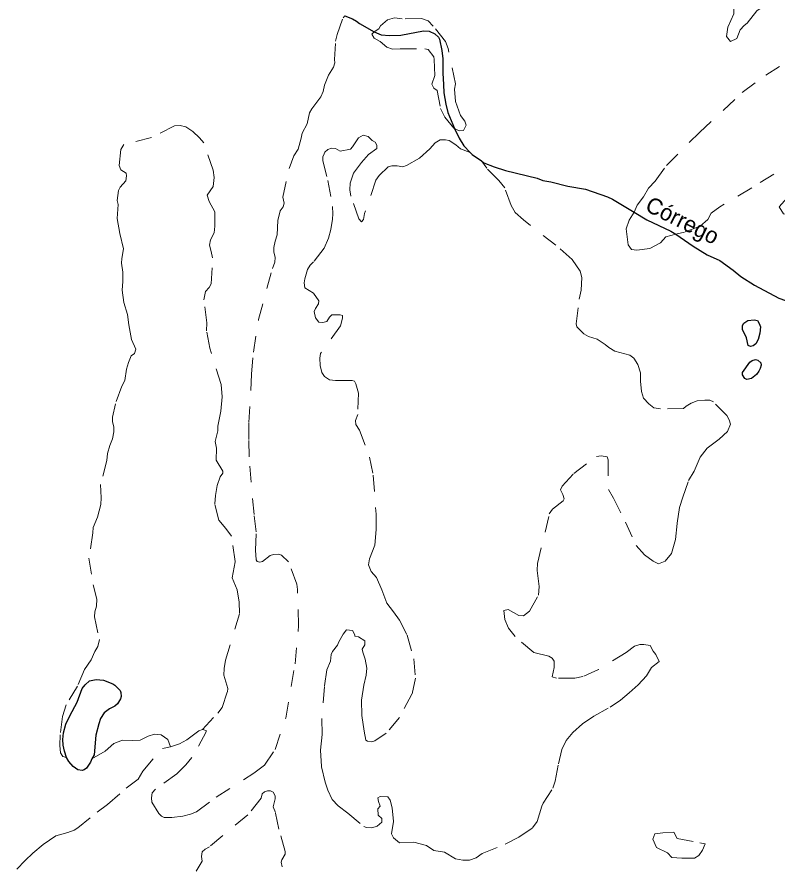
# Model space of a CAD drawing. Extents: x 344.9 to 371, y 7566.4 to 7594.3.
# Drawn here: x 357.38 to 362.09, y 7580.3 to 7585.54 of the extents above; entities that cross this region are included whole.
import ezdxf
from ezdxf.enums import TextEntityAlignment as Align

# ---------------------------------------------------------------- set-up
doc = ezdxf.new("R2010")
doc.units = 0
doc.header["$LTSCALE"] = 0.04
doc.linetypes.add('LONG_DASHED', pattern=[7.5, 6, -1.5])
doc.linetypes.add('SHORT_DASHED', pattern=[2.7, 1.5, -1.2])
for name, color, linetype, lineweight in [('17', 7, 'SHORT_DASHED', 13), ('2', 7, 'Continuous', 25), ('21', 7, 'SHORT_DASHED', 13), ('3', 7, 'LONG_DASHED', 25), ('7', 7, 'Continuous', 25)]:
    doc.layers.add(name, color=color, linetype=linetype, lineweight=lineweight)
doc.layers.add('61', color=7, linetype='Continuous')

msp = doc.modelspace()

# ---------------------------------------------------------------- linework, layer by layer
at = {"layer": '17'}
for points in [[(358.5305, 7581.1294), (358.624, 7581.2313), (358.6522, 7581.266), (358.684, 7581.3637), (358.6877, 7581.384), (358.6618, 7581.4653), (358.6636, 7581.507), (358.6729, 7581.5587), (358.7596, 7581.8497), (358.7577, 7581.9172), (358.7448, 7581.9948), (358.7134, 7582.0687), (358.7319, 7582.1694), (358.7097, 7582.3256), (358.6747, 7582.3736), (358.6304, 7582.4254), (358.6064, 7582.5261), (358.6101, 7582.5779), (358.6202, 7582.6401), (358.6396, 7582.6933), (358.6562, 7582.7154), (358.6562, 7582.7293), (358.6147, 7582.7954), (358.6165, 7582.8716), (358.6082, 7582.9122), (358.6239, 7582.9783), (358.6248, 7583.0078), (358.6433, 7583.0997), (358.6507, 7583.1889), (358.6445, 7583.2656), (358.5749, 7583.4905), (358.5548, 7583.5963), (358.5557, 7583.6469), (358.5391, 7583.7889), (358.5487, 7583.8395), (358.5714, 7583.8643), (358.5836, 7583.887), (358.5923, 7584.0482), (358.5845, 7584.0879), (358.5723, 7584.1262), (358.5793, 7584.1593), (358.6011, 7584.2029), (358.6054, 7584.2443), (358.6063, 7584.3341), (358.5706, 7584.3968), (358.5593, 7584.4369), (358.5959, 7584.4901), (358.6012, 7584.5454), (358.5951, 7584.5908), (358.5376, 7584.7603), (358.5123, 7584.7908), (358.4696, 7584.83), (358.4261, 7584.8597), (358.3921, 7584.8684), (358.3572, 7584.8649), (358.2152, 7584.793), (358.0427, 7584.7507), (358.0244, 7584.7185), (358.0148, 7584.6209), (358.0235, 7584.5921), (358.0566, 7584.5729), (358.0601, 7584.5568), (358.0558, 7584.5254), (358.02, 7584.4853), (358.0096, 7584.4653), (358.0026, 7584.4025), (358.0087, 7584.3781), (358.0018, 7584.2923), (358.0184, 7584.199), (358.0402, 7584.1036), (358.0297, 7584.0453), (358.0288, 7584.0156), (358.0376, 7583.959), (358.0376, 7583.9015), (358.0333, 7583.8488), (358.0429, 7583.773), (358.0656, 7583.6976), (358.0735, 7583.6348), (358.09, 7583.5433), (358.117, 7583.4823), (358.1092, 7583.4566), (358.0883, 7583.4426), (358.0717, 7583.4008)], [(358.0717, 7583.4008), (358.0595, 7583.359), (358.0482, 7583.2884), (358.0316, 7583.2535), (357.9907, 7583.145), (357.9724, 7583.0631), (357.9733, 7583.0339), (357.9812, 7583.0034), (357.9803, 7582.9711), (357.9733, 7582.9284), (357.9567, 7582.8875), (357.9419, 7582.8369), (357.9384, 7582.7933), (357.8992, 7582.6465), (357.9037, 7582.5632), (357.901, 7582.5214), (357.8801, 7582.4438), (357.8531, 7582.3802), (357.8522, 7582.3471), (357.8272, 7582.1903), (357.8532, 7582.0255), (357.875, 7581.9366), (357.8733, 7581.8926), (357.8628, 7581.8586), (357.862, 7581.8264), (357.8916, 7581.6873), (357.8829, 7581.6437), (357.8637, 7581.6115), (357.8402, 7581.5601), (357.7993, 7581.4999), (357.7566, 7581.3984), (357.6852, 7581.2825), (357.6635, 7581.2106), (357.6496, 7581.0968), (357.6461, 7581.0315), (357.6505, 7580.9844), (357.6653, 7580.9635), (357.6886, 7580.9566)], [(357.846, 7580.9479), (357.9268, 7580.9965), (357.9811, 7581.0433), (358.034, 7581.0644), (358.0989, 7581.0614), (358.1442, 7581.0644), (358.194, 7581.0886), (358.2333, 7581.1006), (358.2741, 7581.0976), (358.3163, 7581.0674), (358.3319, 7581.0215)]]:
    msp.add_lwpolyline(points, dxfattribs=at)
at = {"layer": '2'}
for points in [[(361.9681, 7583.544), (361.955, 7583.5169), (361.9384, 7583.5042), (361.9209, 7583.5002), (361.9066, 7583.5066), (361.8971, 7583.5542), (361.8724, 7583.605), (361.8716, 7583.6289), (361.8804, 7583.6432), (361.9042, 7583.6598), (361.9447, 7583.6646), (361.9645, 7583.6598), (361.9749, 7583.6424), (361.9823, 7583.6208), (361.9788, 7583.582)], [(361.9269, 7583.3017), (361.8996, 7583.2962), (361.8867, 7583.3008), (361.8713, 7583.3241), (361.8727, 7583.3389), (361.9167, 7583.4028), (361.9319, 7583.4139), (361.9518, 7583.419), (361.9662, 7583.4153), (361.9856, 7583.3981), (361.987, 7583.3842), (361.9809, 7583.3629), (361.9735, 7583.3467), (361.9587, 7583.3272)]]:
    msp.add_lwpolyline(points, close=True, dxfattribs=at)
at = {"layer": '21'}
for points in [[(362.1042, 7585.6456), (362.0474, 7585.6125), (361.9883, 7585.5959), (361.9599, 7585.577), (361.9008, 7585.5013), (361.8818, 7585.4871), (361.8582, 7585.4587), (361.8369, 7585.4067), (361.7967, 7585.3878), (361.773, 7585.4185), (361.7801, 7585.4753), (361.818, 7585.5581), (361.818, 7585.5912), (361.8132, 7585.6267), (361.7896, 7585.6952)], [(359.0196, 7582.2093), (358.9991, 7582.2152), (358.9694, 7582.2133), (358.949, 7582.2067), (358.9002, 7582.1691), (358.8843, 7582.1644), (358.8685, 7582.1697), (358.8626, 7582.179), (358.8586, 7582.2397), (358.8626, 7582.3528), (358.8488, 7582.4603), (358.8184, 7582.8171), (358.8164, 7582.9247), (358.817, 7583.0285), (358.8341, 7583.3295), (358.8453, 7583.4641), (358.8769, 7583.6663), (358.9621, 7583.9825), (358.9779, 7584.0221), (358.9792, 7584.0512), (358.9724, 7584.0863), (358.9724, 7584.1134), (358.979, 7584.151), (358.9922, 7584.1912), (358.9955, 7584.2792), (359.01, 7584.3386), (359.0291, 7584.3636), (359.0357, 7584.3867), (359.0272, 7584.4237), (359.0654, 7584.6007), (359.0951, 7584.6792), (359.1221, 7584.7218), (359.1412, 7584.7891), (359.1465, 7584.8201), (359.1782, 7584.8781), (359.1931, 7584.9457), (359.2063, 7584.9708), (359.2631, 7585.0441), (359.2769, 7585.0784), (359.2848, 7585.1166), (359.3104, 7585.1795), (359.3408, 7585.229), (359.348, 7585.2548), (359.3467, 7585.2759), (359.3538, 7585.389), (359.3623, 7585.4306), (359.3999, 7585.5335), (359.4101, 7585.5457)], [(359.7662, 7585.5269), (359.7179, 7585.5328), (359.6742, 7585.5223), (359.6314, 7585.4833), (359.6203, 7585.4666), (359.5922, 7585.4468)], [(360.0897, 7584.8482), (360.1189, 7584.8348), (360.1449, 7584.8367), (360.1616, 7584.8692), (360.1532, 7584.8934), (360.1272, 7584.9287), (360.0966, 7585.0151), (360.09, 7585.0932), (360.0956, 7585.1258), (360.0501, 7585.3437), (360.0343, 7585.3874), (359.958, 7585.4826), (359.9255, 7585.5142), (359.8846, 7585.53), (359.7662, 7585.5269)], [(359.5922, 7585.4468), (359.5785, 7585.4322), (359.5924, 7585.4089), (359.6286, 7585.3866), (359.6705, 7585.3522), (359.7058, 7585.3392), (359.7541, 7585.342), (359.9061, 7585.3421), (359.9265, 7585.3374), (359.9609, 7585.2928), (359.9637, 7585.2751), (359.9683, 7585.177), (359.9498, 7585.1231), (359.9618, 7585.098), (359.9814, 7585.085), (360.0027, 7584.9719), (360.0287, 7584.918), (360.0845, 7584.8506), (360.0897, 7584.8482)], [(361.2019, 7584.3321), (361.2196, 7584.3754), (361.2598, 7584.4251), (361.2906, 7584.4795), (361.3308, 7584.5221), (361.4018, 7584.619), (361.6052, 7584.8248), (361.8701, 7585.0709), (362.0168, 7585.1797), (362.1824, 7585.2826)], [(360.1863, 7584.7004), (360.1259, 7584.7237), (360.0971, 7584.7475), (360.0565, 7584.7745), (360.0328, 7584.7796), (360.0006, 7584.7796), (359.9702, 7584.761), (359.9363, 7584.7237), (359.872, 7584.6662), (359.7924, 7584.6205), (359.7704, 7584.612), (359.7348, 7584.6171), (359.701, 7584.6171), (359.679, 7584.612), (359.6231, 7584.5578), (359.6028, 7584.529), (359.5333, 7584.3225), (359.5265, 7584.2852), (359.5147, 7584.2717), (359.4977, 7584.2903), (359.4469, 7584.4308), (359.4419, 7584.4698), (359.4436, 7584.5104), (359.4639, 7584.573), (359.5147, 7584.6391), (359.557, 7584.6882), (359.6094, 7584.7246), (359.6094, 7584.7449), (359.5976, 7584.7635), (359.579, 7584.7754), (359.5553, 7584.7991), (359.5248, 7584.8076), (359.496, 7584.7906), (359.4588, 7584.7348), (359.4452, 7584.7212), (359.3809, 7584.7094), (359.3521, 7584.7246), (359.3284, 7584.7263), (359.3047, 7584.7195), (359.2878, 7584.7026), (359.2827, 7584.6924), (359.2742, 7584.6738), (359.2742, 7584.6484), (359.3064, 7584.5265), (359.3352, 7584.3657), (359.3369, 7584.3216), (359.3335, 7584.2869), (359.3234, 7584.2242), (359.3098, 7584.1701), (359.2827, 7584.1074), (359.2167, 7584.0228), (359.1964, 7584.0025), (359.1794, 7583.9754), (359.1625, 7583.9178), (359.1591, 7583.8933), (359.1625, 7583.8628), (359.2167, 7583.8306), (359.2505, 7583.7815), (359.2488, 7583.7629), (359.2285, 7583.7358), (359.2218, 7583.7155), (359.2285, 7583.6782), (359.2505, 7583.6511), (359.2742, 7583.6478), (359.2996, 7583.6545), (359.3166, 7583.6816), (359.3301, 7583.6952), (359.3809, 7583.6952), (359.3961, 7583.6918), (359.3961, 7583.6748), (359.3843, 7583.6274), (359.2607, 7583.4564), (359.2556, 7583.4268), (359.259, 7583.3828), (359.2692, 7583.3387), (359.2844, 7583.3133), (359.3166, 7583.293), (359.3538, 7583.2896), (359.4554, 7583.2896), (359.4706, 7583.2846), (359.4791, 7583.2693)], [(362.3884, 7584.3962), (362.3089, 7584.3789), (362.2501, 7584.3564), (362.1844, 7584.3149), (362.1256, 7584.3218), (362.0979, 7584.3633), (362.2259, 7584.5051), (362.3954, 7584.6366), (362.4957, 7584.64), (362.5476, 7584.6573), (362.551, 7584.6712), (362.5234, 7584.6781), (362.423, 7584.685), (362.2881, 7584.6885), (362.2363, 7584.6712), (361.9293, 7584.4819)], [(361.5026, 7582.5684), (361.5381, 7582.67), (361.5737, 7582.7275), (361.6109, 7582.8156), (361.6533, 7582.8714), (361.7278, 7582.9256), (361.7786, 7582.9739), (361.7972, 7583.0196), (361.7888, 7583.045), (361.7752, 7583.0721), (361.6922, 7583.1567), (361.6702, 7583.1686), (361.6381, 7583.1686), (361.5907, 7583.1635), (361.5551, 7583.1499), (361.5229, 7583.1296), (361.5077, 7583.1161), (361.3638, 7583.1144), (361.3232, 7583.1195), (361.2927, 7583.144), (361.2589, 7583.1796), (361.247, 7583.2219), (361.2402, 7583.2846), (361.2402, 7583.3371), (361.225, 7583.3879), (361.1996, 7583.4268), (361.1742, 7583.4454), (361.0811, 7583.4708), (361.0438, 7583.4928), (361.0218, 7583.5123), (360.9727, 7583.5445), (360.9185, 7583.5614), (360.8897, 7583.5783), (360.8474, 7583.6206), (360.8423, 7583.6393), (360.861, 7583.7933), (360.8728, 7583.8475), (360.8779, 7583.9271), (360.8677, 7583.966), (360.8186, 7584.038), (360.717, 7584.126), (360.5155, 7584.2835), (360.4647, 7584.3292), (360.4393, 7584.3724), (360.4004, 7584.4807), (360.3648, 7584.5264), (360.2886, 7584.6026), (360.2565, 7584.6485)], [(361.9293, 7584.4819), (361.7306, 7584.3636), (361.6785, 7584.3257), (361.6572, 7584.2855), (361.6099, 7584.2453), (361.5129, 7584.2075), (361.459, 7584.1943)], [(361.459, 7584.1943), (361.397, 7584.1791), (361.3639, 7584.1412), (361.2977, 7584.1057), (361.2173, 7584.0963), (361.1841, 7584.101), (361.1652, 7584.1294), (361.151, 7584.2287), (361.1699, 7584.2808), (361.2019, 7584.3321)], [(359.4791, 7583.2693), (359.496, 7583.2117), (359.491, 7583.078), (359.4774, 7583.0424), (359.4791, 7583.0162), (359.5011, 7582.9823), (359.5637, 7582.8147), (359.5858, 7582.7029), (359.6044, 7582.4616), (359.6044, 7582.3668), (359.5959, 7582.2703), (359.5637, 7582.1856), (359.5569, 7582.1492), (359.5739, 7582.1069), (359.606, 7582.0696), (359.6399, 7581.9934), (359.6704, 7581.9105), (359.7127, 7581.858), (359.7482, 7581.8072), (359.7973, 7581.7124), (359.8379, 7581.5676), (359.8481, 7581.4474), (359.8261, 7581.3475), (359.7482, 7581.2045), (359.667, 7581.1063), (359.5958, 7581.0589), (359.5772, 7581.0538), (359.5518, 7581.0572), (359.5417, 7581.0639), (359.5298, 7581.1198), (359.5163, 7581.2163), (359.5129, 7581.3111), (359.5281, 7581.4042), (359.5434, 7581.4652), (359.5467, 7581.5092), (359.5366, 7581.5651), (359.5213, 7581.6074), (359.5184, 7581.6277), (359.5354, 7581.6531), (359.5354, 7581.6785), (359.4947, 7581.7039), (359.4727, 7581.7081), (359.4727, 7581.7149), (359.4575, 7581.742), (359.4202, 7581.7471), (359.3999, 7581.72), (359.3745, 7581.6726), (359.366, 7581.6506), (359.3339, 7581.6116), (359.3254, 7581.593), (359.322, 7581.5524), (359.3, 7581.4982), (359.2848, 7581.3949), (359.2678, 7581.1977), (359.2712, 7581.0978), (359.2594, 7581.0013), (359.2661, 7580.898), (359.2881, 7580.804), (359.305, 7580.7549), (359.3321, 7580.6957), (359.3694, 7580.6567), (359.4286, 7580.6127), (359.5282, 7580.5293), (359.5454, 7580.5238), (359.5776, 7580.5221), (359.6115, 7580.5306), (359.6402, 7580.556), (359.6402, 7580.578), (359.6165, 7580.6), (359.6149, 7580.6389), (359.6301, 7580.6542), (359.6182, 7580.6846), (359.6149, 7580.7066), (359.6301, 7580.7151), (359.6775, 7580.7134), (359.691, 7580.6914), (359.7029, 7580.6457), (359.7114, 7580.561), (359.6995, 7580.4832), (359.7114, 7580.4594), (359.7486, 7580.429), (359.8383, 7580.4324), (359.9162, 7580.412), (359.9619, 7580.3799), (360.0279, 7580.3706)], [(360.0279, 7580.3706), (360.0957, 7580.3283), (360.1414, 7580.3215), (360.182, 7580.3215), (360.2226, 7580.335), (360.2599, 7580.3621), (360.4021, 7580.4197), (360.4868, 7580.4629), (360.5714, 7580.5204), (360.6019, 7580.5611), (360.6307, 7580.6559), (360.6391, 7580.6728), (360.6984, 7580.7659), (360.7119, 7580.81), (360.7322, 7580.9167), (360.7542, 7581.0064), (360.7813, 7581.0606), (360.8219, 7581.1114), (360.8812, 7581.1639), (360.9523, 7581.213), (361.0522, 7581.2672), (361.1165, 7581.3112), (361.1707, 7581.3569), (361.2266, 7581.406), (361.2774, 7581.4619), (361.3078, 7581.5127), (361.3552, 7581.5499), (361.3349, 7581.5939), (361.3197, 7581.6134), (361.301, 7581.6489), (361.2621, 7581.6557), (361.2367, 7581.6557), (361.2028, 7581.6455), (361.152, 7581.6066), (360.981, 7581.5016), (360.8845, 7581.4567), (360.8337, 7581.4483), (360.7203, 7581.4483), (360.6949, 7581.455), (360.7067, 7581.5143), (360.7067, 7581.5532), (360.6949, 7581.5702), (360.6729, 7581.5837), (360.5814, 7581.6057), (360.4646, 7581.7048), (360.424, 7581.7573), (360.402, 7581.8098), (360.3952, 7581.8656), (360.4206, 7581.8724), (360.4867, 7581.8351), (360.5171, 7581.8335), (360.5544, 7581.8622), (360.6086, 7581.9604), (360.6136, 7582.0146), (360.6018, 7582.1162), (360.6035, 7582.1568), (360.6763, 7582.4641), (360.6966, 7582.4929), (360.7627, 7582.5454), (360.7678, 7582.5573), (360.7594, 7582.5844), (360.7458, 7582.6132), (360.756, 7582.6352), (360.8271, 7582.7131), (360.9693, 7582.8197), (360.9981, 7582.8231), (361.0353, 7582.818), (361.0404, 7582.7994), (361.0421, 7582.6149), (361.0743, 7582.5607), (361.1471, 7582.4125), (361.2131, 7582.2686), (361.2656, 7582.2111), (361.3181, 7582.1704), (361.352, 7582.1552), (361.3943, 7582.1721), (361.4332, 7582.2178), (361.4569, 7582.3059), (361.4671, 7582.4075), (361.4823, 7582.504), (361.5026, 7582.5684)], [(358.5305, 7581.1294), (358.5517, 7581.1232), (358.5536, 7581.1142), (358.464, 7580.9555), (358.4276, 7580.91), (358.3714, 7580.8553), (358.2393, 7580.7612), (358.2181, 7580.7384), (358.2135, 7580.7065), (358.2165, 7580.6792), (358.2606, 7580.6094), (358.2757, 7580.5942), (358.2924, 7580.5851), (358.3395, 7580.5851), (358.4078, 7580.5942), (358.4564, 7580.6048), (358.4926, 7580.6198), (358.6143, 7580.7103), (358.8481, 7580.8599), (358.9134, 7580.9085), (358.9787, 7581.0056), (359.0455, 7581.1992), (359.1031, 7581.5363), (359.1244, 7581.7731), (359.1174, 7581.9955), (359.1128, 7582.0298), (359.0612, 7582.1677), (359.0196, 7582.2093)], [(358.3319, 7581.0215), (358.3881, 7581.0413), (358.4321, 7581.0656), (358.5074, 7581.1207), (358.5305, 7581.1294)], [(357.3815, 7580.2648), (357.4316, 7580.3194), (357.4802, 7580.365), (357.5439, 7580.4181), (357.6221, 7580.472), (357.6969, 7580.4917), (357.7352, 7580.5062), (357.7574, 7580.5207), (357.8773, 7580.6179), (357.9426, 7580.6665), (358.058, 7580.7667), (358.1309, 7580.8213), (358.1597, 7580.8715), (358.2818, 7581.0124), (358.3319, 7581.0215)], [(359.0235, 7580.2794), (359.0172, 7580.3093), (359.0204, 7580.3235), (359.0424, 7580.3581), (359.0424, 7580.3753), (359.0015, 7580.5137), (358.9811, 7580.6159), (358.9669, 7580.6505), (358.9795, 7580.7008), (358.9795, 7580.7181), (358.9669, 7580.7417), (358.9509, 7580.7502), (358.9315, 7580.7502), (358.9135, 7580.7437), (358.8997, 7580.7319), (358.8932, 7580.7042), (358.8097, 7580.601), (358.5724, 7580.4037), (358.5456, 7580.3896), (358.5283, 7580.3723), (358.5236, 7580.344), (358.5283, 7580.3157), (358.4906, 7580.2528)]]:
    msp.add_lwpolyline(points, dxfattribs=at)
msp.add_lwpolyline([(361.4349, 7580.3381), (361.407, 7580.3661), (361.34, 7580.3997), (361.3177, 7580.4501), (361.3289, 7580.4837), (361.3791, 7580.4893), (361.4461, 7580.4949), (361.4684, 7580.4557), (361.608, 7580.4277), (361.6415, 7580.4221), (361.6248, 7580.3829), (361.6024, 7580.3493), (361.5745, 7580.3325), (361.4964, 7580.3325)], close=True, dxfattribs=at)
at = {"layer": '3'}
msp.add_line((357.7029, 7580.9313), (357.6886, 7580.9566), dxfattribs=at)
for points in [[(357.6886, 7580.9566), (357.6755, 7580.9945), (357.6677, 7581.033), (357.6651, 7581.0684), (357.6694, 7581.1091), (357.6833, 7581.1626), (357.7079, 7581.2145), (357.7539, 7581.2986), (357.7857, 7581.3833), (357.8029, 7581.407), (357.8301, 7581.4311), (357.8717, 7581.4392), (357.917, 7581.435), (357.9759, 7581.4118), (357.9883, 7581.4034), (358.0204, 7581.3701), (358.0253, 7581.3581), (358.0258, 7581.3331), (358.0218, 7581.3184), (358.0032, 7581.2879), (357.9875, 7581.274), (357.9545, 7581.257), (357.9215, 7581.2335), (357.8995, 7581.1986), (357.8874, 7581.1644), (357.8706, 7581.0947), (357.8588, 7580.9732), (357.846, 7580.9479)], [(357.846, 7580.9479), (357.8371, 7580.9279), (357.8111, 7580.8903), (357.797, 7580.8792), (357.7861, 7580.875), (357.7583, 7580.8797), (357.7297, 7580.9004), (357.7029, 7580.9313)]]:
    msp.add_lwpolyline(points, dxfattribs=at)
at = {"layer": '7'}
for points in [[(359.4101, 7585.5457), (359.4592, 7585.5283), (359.483, 7585.5141), (359.5013, 7585.4981), (359.5922, 7585.4468)], [(359.5922, 7585.4468), (359.6355, 7585.4291), (359.6879, 7585.4235), (359.7578, 7585.4259), (359.8976, 7585.4537), (359.9325, 7585.4521), (359.9675, 7585.4354), (359.9897, 7585.4132), (359.996, 7585.4013), (360.0119, 7585.3314), (360.0167, 7585.279), (360.0167, 7585.1917), (360.0222, 7585.1218)], [(360.0222, 7585.1218), (360.0238, 7585.0694), (360.0349, 7584.9995), (360.0492, 7584.9471), (360.0897, 7584.8482)], [(360.0897, 7584.8482), (360.1183, 7584.7899), (360.1469, 7584.7422), (360.1863, 7584.7004)], [(360.1863, 7584.7004), (360.1985, 7584.6874), (360.2565, 7584.6485)], [(360.2565, 7584.6485), (360.2716, 7584.6374), (360.3343, 7584.6119), (360.4042, 7584.5889), (360.6003, 7584.5405), (360.6361, 7584.5278), (360.6853, 7584.519), (360.7901, 7584.4928), (360.8997, 7584.473), (361.0363, 7584.4254), (361.0667, 7584.4122), (361.2019, 7584.3321)], [(361.2019, 7584.3321), (361.2807, 7584.2833), (361.4279, 7584.2145), (361.459, 7584.1943)], [(361.459, 7584.1943), (361.5672, 7584.1213), (361.6541, 7584.068), (361.7307, 7584.0313), (361.8151, 7583.9715), (361.8608, 7583.932), (361.9452, 7583.8788), (362.0975, 7583.7994), (362.1736, 7583.7715)]]:
    msp.add_lwpolyline(points, dxfattribs=at)

# ---------------------------------------------------------------- texts
at = {"layer": '61'}
msp.add_text('Córrego', height=0.1, rotation=333.416, dxfattribs=at).set_placement((361.4782, 7584.2357), align=Align.CENTER)

doc.saveas('drawing.dxf')
